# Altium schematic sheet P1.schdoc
size 297 x 209 mm; Symbol: Drawing-Symbol_A4; Company: 嘉立创EDA; Drawed: Tacoin; Version: V1.0; Page Size: A4; @Project Name: T-Mesh; @Update Date: 2026-08-26; @Create Date: 2026-08-26; Device: Drawing-Symbol_A4; @Board Name: Board1; @Page Name: P1; @Create Time: 20:35:45; @Page Count: 1; @Page No: 1; @Schematic Name: Schematic1; @Update Time: 20:35:45; @Assembly Variant: Basic; Border: 1; Title Block Position: 3; Size: A4; Width: 1170; Height: 825; Region Start: 1; X Region Count: 6; Y Region Count: 4; Blade Width: 10
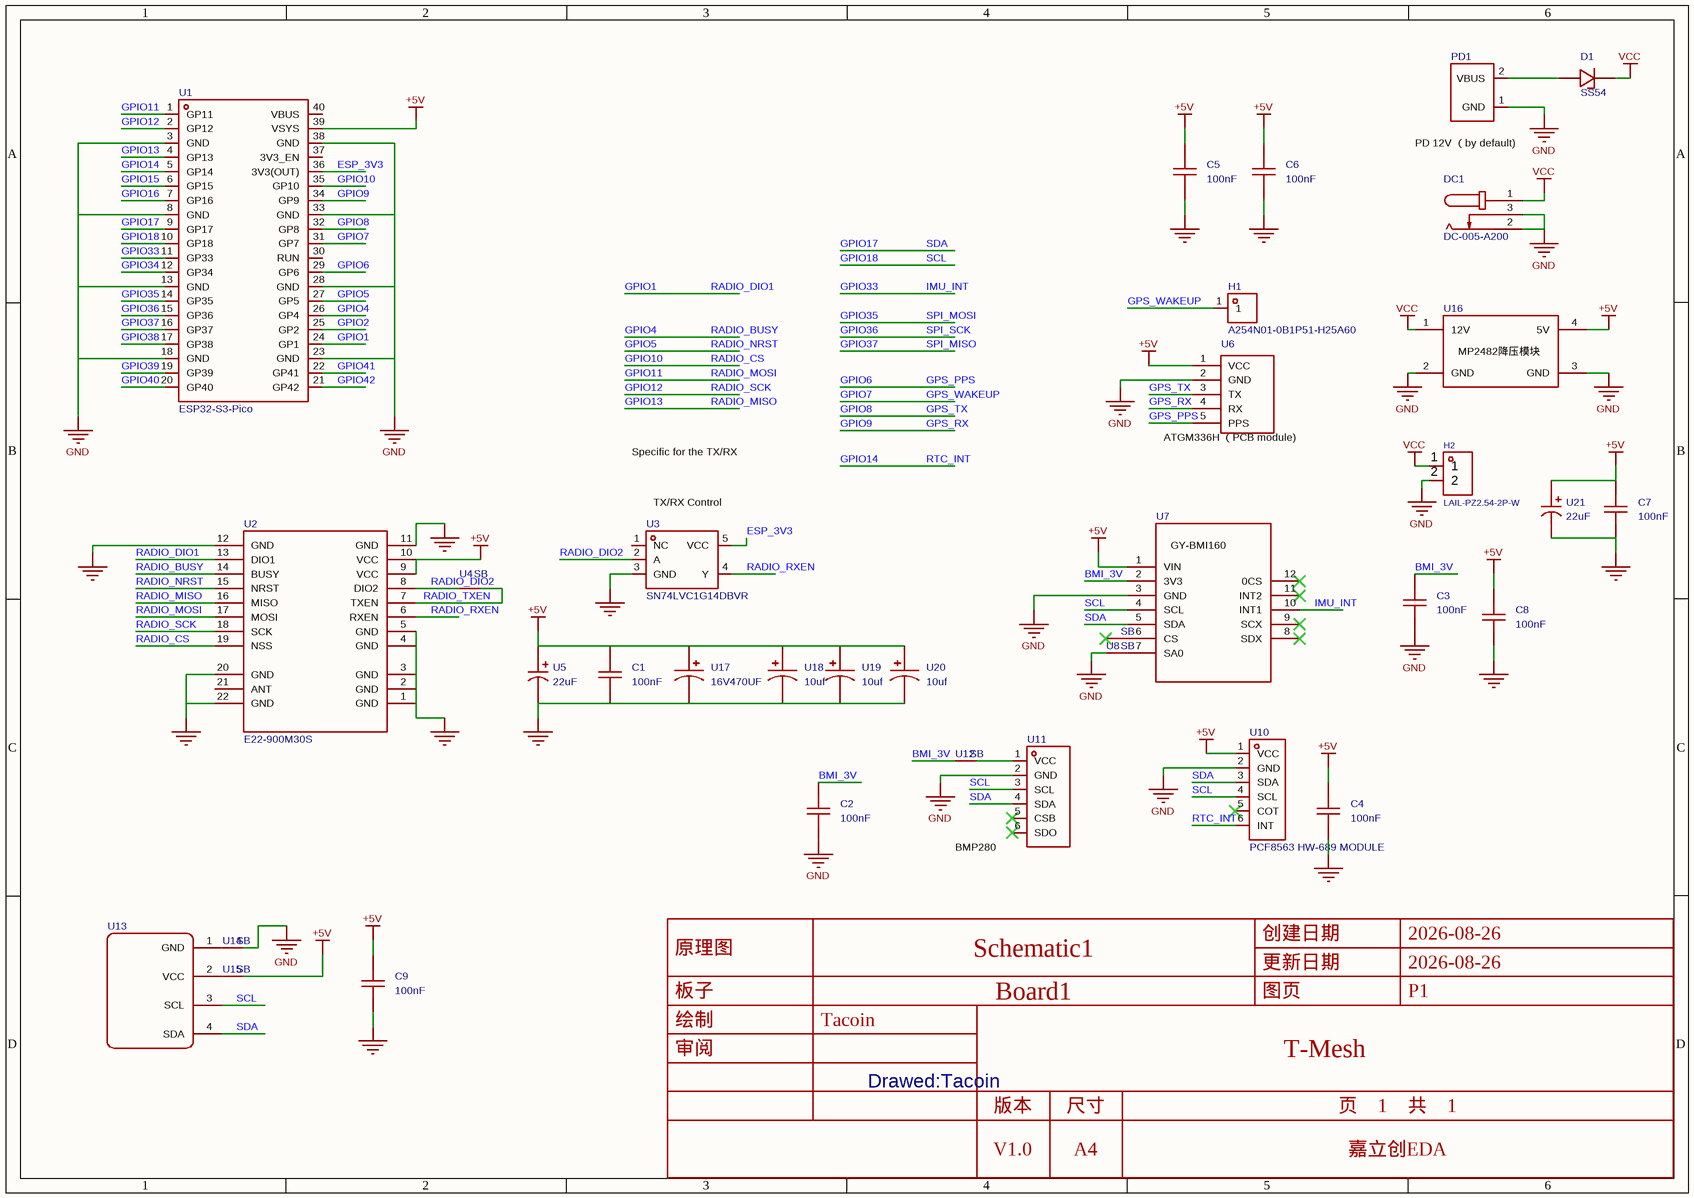
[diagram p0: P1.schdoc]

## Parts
C1  100nF  [C0603]
C2  100nF  [C0603]
C3  100nF  [C0603]
C4  100nF  [C0603]
C5  100nF  [C0603]
C6  100nF  [C0603]
C7  100nF  [C0603]
C8  100nF  [C0603]
C9  100nF  [C0603]
D1  SS54  [SMA_L4.3-W2.6-LS5.0-FD]
DC1  DC-005-A200  [DC-IN-TH_DC-005-A200]
H1  A254N01-0B1P51-H25A60  [HDR-TH_1P-P2.54-V-M-3]
H2  LAIL-PZ2.54-2P-W  [HDR-TH_2P-P2.54-H-M-W10.0]
PD1  (no value)  [PDC004-PD诱骗模块]
U1  ESP32-S3-Pico  [LCC-40_L51.0-W21.0-P2.54-BL_RP2040-BASED]
U2  E22-900M30S  [WIRELM-SMD_E22-900M30S]
U3  SN74LVC1G14DBVR  [SOT-23-5_L3.0-W1.7-P0.95-LS2.8-BR]
U4  (no value)  [SB]
U5  22uF  [CAP-SMD_BD4.0-L4.3-W4.3-LS5.0-FD]
U6  (no value)  [ATGM336H]
U7  (no value)  [GY-BMI160]
U8  (no value)  [SB]
U9  (no value)  [SB]
U10  PCF8563 HW-689 MODULE  [PCF8563-I2C-2.54-1*6]
U11  (no value)  [GY-BMP280]
U12  (no value)  [SB]
U13  (no value)  [OLED 0.96寸]
U14  (no value)  [SB]
U15  (no value)  [SB]
U16  (no value)  [MP2482]
U17  16V470UF  [CAP-SMD_BD8.0-L8.3-W8.3-LS9.3-FD]
U18  10uf  [CAP-SMD_L2.0-W1.3-FD]
U19  10uf  [CAP-SMD_L2.0-W1.3-FD]
U20  10uf  [CAP-SMD_L2.0-W1.3-FD]
U21  22uF  [CAP-SMD_BD4.0-L4.3-W4.3-LS5.0-FD]

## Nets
+5V: C1.2 C4.2 C5.2 C6.2 C7.2 C8.2 C9.2 U1.39(VSYS) U2.9(VCC) U2.10(VCC) U5.1 U6.1(VCC) U7.1(VIN) U10.1(VCC) U15.2 U16.4(5V) U17.1 U18.1 U19.1 U20.1 U21.1
GND: C1.1 C2.1 C3.1 C4.1 C5.1 C6.1 C7.1 C8.1 C9.1 DC1.2 DC1.3 H2.2 PD1.1(GND) U1.3(GND) U1.8(GND) U1.13(GND) U1.18(GND) U1.23(GND) U1.28(GND) U1.33(GND) U1.38(GND) U2.1(GND) U2.2(GND) U2.3(GND) U2.4(GND) U2.5(GND) U2.11(GND) U2.12(GND) U2.20(GND) U2.22(GND) U3.3(GND) U5.2 U6.2(GND) U7.3(GND) U8.1 U10.2(GND) U11.2(GND) U14.2 U16.2(GND) U16.3(GND) U17.2 U18.2 U19.2 U20.2 U21.2
VCC: D1.2(K) DC1.1 H2.1 U16.1(12V)
BMI_3V: C2.2 C3.2 U7.2(3V3) U12.1
ESP_3V3: U1.36(3V3(OUT)) U3.5(VCC)
GPIO1: U1.24(GP1) U2.13(DIO1)  [also labelled RADIO_DIO1]
GPIO2: U1.25(GP2)
GPIO4: U1.26(GP4) U2.14(BUSY)  [also labelled RADIO_BUSY]
GPIO5: U1.27(GP5) U2.15(NRST)  [also labelled RADIO_NRST]
GPIO6: U1.29(GP6) U6.5(PPS)  [also labelled GPS_PPS]
GPIO7: H1.1 U1.31(GP7)  [also labelled GPS_WAKEUP]
GPIO8: U1.32(GP8) U6.3(TX)  [also labelled GPS_TX]
GPIO9: U1.34(GP9) U6.4(RX)  [also labelled GPS_RX]
GPIO10: U1.35(GP10) U2.19(NSS)  [also labelled RADIO_CS]
GPIO11: U1.1(GP11) U2.17(MOSI)  [also labelled RADIO_MOSI]
GPIO12: U1.2(GP12) U2.18(SCK)  [also labelled RADIO_SCK]
GPIO13: U1.4(GP13) U2.16(MISO)  [also labelled RADIO_MISO]
GPIO14: U1.5(GP14) U10.6(INT)  [also labelled RTC_INT]
GPIO15: U1.6(GP15)
GPIO16: U1.7(GP16)
GPIO17: U1.9(GP17) U7.5(SDA) U10.3(SDA) U11.4(SDA) U13.4(SDA)  [also labelled SDA]
GPIO18: U1.10(GP18) U7.4(SCL) U10.4(SCL) U11.3(SCL) U13.3(SCL)  [also labelled SCL]
GPIO33: U1.11(GP33) U7.10(INT1)  [also labelled IMU_INT]
GPIO34: U1.12(GP34)
GPIO35: U1.14(GP35)  [also labelled SPI_MOSI]
GPIO36: U1.15(GP36)  [also labelled SPI_SCK]
GPIO37: U1.16(GP37)  [also labelled SPI_MISO]
GPIO38: U1.17(GP38)
GPIO39: U1.19(GP39)
GPIO40: U1.20(GP40)
GPIO41: U1.22(GP41)
GPIO42: U1.21(GP42)
RADIO_DIO2: U2.8(DIO2) U3.2(A) U4.1
RADIO_RXEN: U2.6(RXEN) U3.4(Y)
RADIO_TXEN: U2.7(TXEN) U4.2
NetD1_1: D1.1(A) PD1.2(VBUS)
NetU7_6: U7.6(CS) U9.2
NetU7_7: U7.7(SA0) U8.2
NetU11_1: U11.1(VCC) U12.2
NetU13_1: U13.1(GND) U14.1
NetU13_2: U13.2(VCC) U15.1

Not connected (* = marked no-connect by the designer): U1 30(RUN) 37(3V3_EN) 40(VBUS); U2 21(ANT); U3 1(NC); U7 8(SDX)* 9(SCX)* 11(INT2)* 12(0CS)*; U9 1*; U10 5(COT)*; U11 5(CSB)* 6(SDO)*

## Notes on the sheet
- PD 12V （by default)
- Specific for the TX/RX
- (near U3) TX/RX Control
- (near U6) ATGM336H （PCB module)
- (near U11) BMP280

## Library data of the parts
C1 = CGA0603X7R104K500JT: 容值:100nF;精度:±10%;额定电压:50V;温度系数:X7R;; Manufacturer: HRE(芯声); AddInBom: yes; ModelId: ac125912035d415993ca9572d50418b10819f05c4eef4c71ace90d822a990e87; ModelName: C0603_L1.6-W0.8-H0.8; ModelTransform: 62.992,31.496,0,0,0,0,0,0,0; Tolerance: ±10%; Voltage Rating: 50V; Temperature Coefficient: X7R
C2-C9 = CGA0603X7R104K500JT: 容值:100nF;精度:±10%;额定电压:50V;温度系数:X7R;; Manufacturer: HRE(芯声); 3D Model: ac125912035d415993ca9572d50418b10819f05c4eef4c71ace90d822a990e87; 3D Model Transform: 62.992,31.496,0,0,0,0,0,0,0; Tolerance: ±10%; Voltage Rating: 50V; Temperature Coefficient: X7R; AddInBom: yes; ModelName: C0603_L1.6-W0.8-H0.8
D1 = SS54_C7420369: 二极管配置:独立式;正向压降(Vf):550mV@5A;直流反向耐压(Vr):40V;整流电流:5A;; Manufacturer: R+O(宏嘉诚); AddInBom: yes; ModelId: 7e24bebe6cd74171ae8c9de6fc5b78aa0819f05c4eef4c71ace90d822a990e87; ModelTransform: 198.4248,103.5431,0,180,0,0,-0.001,0,0; Diode Configuration: 独立式; Voltage - DC Reverse(Vr): 40V; Current - Rectified: 5A; Reverse Leakage Current (Ir): 50uA@40V; Operating Junction Temperature Range: -55℃~+125℃; Non-Repetitive Peak Forward Surge Current: 120A
DC1 = DC-005-A200: 连接器类型:DC电源插座;安装方式:弯插;触点内径:2mm;触点外径:6.4mm;额定电流:3A;额定电压:30V;工作温度:-20℃~+70℃;; Manufacturer: XUNPU(讯普); AddInBom: yes; ModelId: 1321cdbe1dc84555a9684967491c86700819f05c4eef4c71ace90d822a990e87; ModelTransform: 553.149,368.14887,0,0,0,0,-137.795,85.63,-161.417; Connector Type: DC电源插座; Inside Contact Diameter: 2mm; Outside Contact Diameter: 6.4mm; Current Rating: 3A; Voltage Rating (Max): 30V
H1 = A254N01-0B1P51-H25A60: 插针结构:1x1P;间距:2.54mm;圆针/方针:方针;安装方式:直插;排数:单排;总PIN位数:1P;额定电流:3A;额定电压:1kV;配合针长度:6mm;塑高:2.5mm;端接针长度:3mm;触头材质:黄铜;触头镀层:金;工作温度:-40℃~+105℃;颜色:黑色;; Manufacturer: JXTCONN(聚兴泰); AddInBom: yes; ModelId: e328d1a16ef6449e8f36c5b21a72766f0819f05c4eef4c71ace90d822a990e87; ModelTransform: 100.394,100,0,0,0,0,0,0,-118.11; Pin Structure: 1x1P; Pitch: 2.54mm; Circluar Pins/Square Pins: 方针; Current Rating: 3A; Voltage Rating (Max): 1kV
H2 = LAIL-PZ2.54-2P-W: 插针结构:1x2P;间距:2.54mm;圆针/方针:方针;排数:单排;总PIN位数:2P;额定电流:3A;额定电压:250V;塑高:2.5mm;触头材质:黄铜;触头镀层:金;工作温度:-25℃~+80℃;颜色:黑色;; Manufacturer: LAILAN(莱联); AddInBom: yes; ModelId: 7f8eef78e7c94d4693055d9f6a57d1560819f05c4eef4c71ace90d822a990e87; ModelName: HDR-TH_2P-P2.54-M-WI-1X2P; ModelTransform: 200,409.448,0,180,0,0,0,190.945,-118.11; Pin Structure: 1x2P; Pitch: 2.54mm; Circluar Pins/Square Pins: 方针; Current Rating: 3A; Voltage Rating (Max): 250V
PD1 = PDC004-PD诱骗模块: AddInBom: yes; ModelTransform: 0, 0, 0, 0, 0, 0, 0, 0, 0
U1 = ESP32-S3-Pico: 开发板  产品特性是一款体积小巧，搭载多种数字接口的微控制器开发板。在硬件上，采用 ESP32-S3R2 为主芯片，其搭载 Xtensa 32 位 LX7 双核处理器的主频高达 240MHz，内置 512KB SRAM（TCM）和 2MB PSRAM；接口芯片采用 CH343 与 CH334，可通过 USB-C 口进行 USB 和 UART 开发；DC-DC 芯片采用 MP28164，高效率降压-升压芯片，负载电流可达 2A，能保障产品使用安全。在软件上，可选择 ESP-IDF、Arduino、Micro; Manufacturer: Waveshare(微雪电子); AddInBom: yes
U2 = E22-900M30S: 发射功率:31dBm;接口类型:SPI;接收灵敏度:-151dBm;通讯距离:12km;; Manufacturer: EBYTE(亿佰特); AddInBom: yes; ModelId: 425a40043bbc47c1961abccfe65c6b290819f05c4eef4c71ace90d822a990e87; ModelName: WIRELM-SMD_L38.5-W24.0-H3.9-E22-900M30S; ModelTransform: 944.88,1515.745,0,0,0,0,0,-55.514,0; Output Power: 31dBm; Interface Type: SPI; Modulation System: LoRa; Voltage - Supply: 2.5V~5.5V; Antenna Type: IPEX接口; Receive  Current: 14mA; Send  Current: 650mA; Communication Distance: 12km
U3 = SN74LVC1G14DBVR_C434069: 输入类型:施密特触发器;工作电压:1.65V~5.5V;静态电流(Iq):10uA;通道数:1;传播延迟(tpd):20ns@5V,15pF;; Manufacturer: UMW(友台半导体); AddInBom: yes; ModelId: 0a2a1b8f50944f73965918ad6e5fe1670819f05c4eef4c71ace90d822a990e87; ModelName: SOT-23-5_L2.9-W1.6-H1.1-LS2.8-P0.95; ModelTransform: 114.173,109.636,0,180,0,0,0,0,0; Input Type: 施密特触发器; Quiescent Current(Iq): 10uA; Number of Circuits: 1; Current - Output Low(IOL): 32mA; Input Logic Level - High: 1V~3V; Input Logic Level -Low: 500mV~1.9V
U4 U8 U9 U12 U14 U15 = SB: Add into BOM: no; ConvertToPcb: yes
U5 = RVT1A220M0405 22UF 10V: 容值:22uF;精度:±20%;额定电压:10V;纹波电流:21mA@120Hz;等效串联电阻(ESR):-;; Manufacturer: DMBJ(振宝佳); AddInBom: yes; ModelId: d5abac2407cc4bb7a22453350802a0e20819f05c4eef4c71ace90d822a990e87; ModelName: CAP-SMD_L4.3-W4.3-H5.3-LS5.1; ModelTransform: 169.291,181.102,0,90,0,0,0.376,-0.001,0; Tolerance: ±20%; Voltage Rating: 10V; Lifetime: 2800hrs@105℃
U6 = ATGM336H: AddInBom: yes
U7 = GY-BMI160: AddInBom: yes
U10 = PCF8563 HW-689 MODULE: AddInBom: yes
U11 = GY-BMP280: AddInBom: yes
U13 = OLED 0.96: Add into BOM: yes; 3D Model: 1ea46f47a12c4f32ae95110c98e54670ef87cbdfd3ac4685a82c52003a7c100b; 3D Model Transform: 1045.27,989.17,340.16,0,0,0,-27.6,-12.24,0; ModelName: OLED4P
U16 = MP2482: AddInBom: yes
U17 = 16V470UF: AddInBom: yes; ModelId: ae37c166a99f49b1b935231edf05d58d0819f05c4eef4c71ace90d822a990e87; ModelTransform: 366.141,326.771,0,0,0,0,0,0,0
U18-U20 = 10uf: Symbol: 10UF_C9900016685; AddInBom: yes; ModelId: 1f26856de1634853a779dc49a005d0a10819f05c4eef4c71ace90d822a990e87; ModelTransform: 78.74,49.2125,0,0,0,0,0,-0.551,0
U21 = RVT1A220M0405 22UF 10V: 容值:22uF;精度:±20%;额定电压:10V;纹波电流:21mA@120Hz;等效串联电阻(ESR):-;; Manufacturer: DMBJ(振宝佳); 3D Model: d5abac2407cc4bb7a22453350802a0e20819f05c4eef4c71ace90d822a990e87; 3D Model Transform: 169.291,181.102,0,90,0,0,0.376,-0.001,0; Tolerance: ±20%; Voltage Rating: 10V; Lifetime: 2800hrs@105℃; AddInBom: yes; ModelName: CAP-SMD_L4.3-W4.3-H5.3-LS5.1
